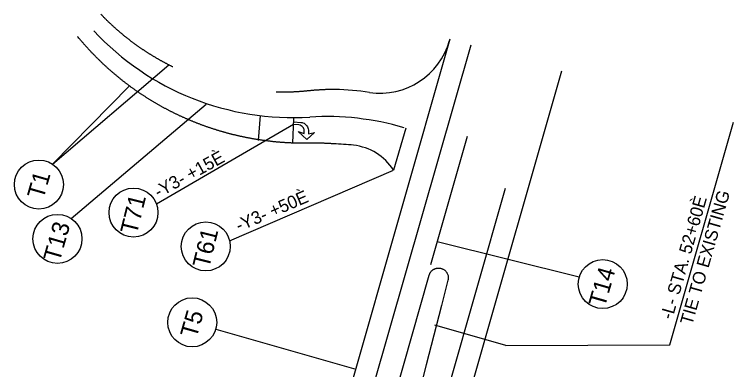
# Model space of a CAD drawing. Extents: x 1657109 to 2100937, y 684916 to 883211.
# Drawn here: x 2097689.9 to 2098086.6, y 689238.5 to 689434.2 of the extents above; entities that cross this region are included whole.
import ezdxf

# ---------------------------------------------------------------- set-up
doc = ezdxf.new("R2010")
doc.units = 0
for name, color, linetype in [('Prop CMT Pvmt Gravel', 7, 'Continuous'), ('Prop Conc 1ft 6in Curb and Gutter', 7, 'Continuous'), ('Prop Dimension', 7, 'Continuous'), ('Prop EOT', 7, 'Continuous'), ('Prop Guardrail Anchor Unit CELL', 7, 'Continuous'), ('Prop Lane Arrow CELL', 7, 'Continuous'), ('Prop Lane Lines', 7, 'Continuous'), ('Prop VPT Ditch Grade Right Label', 7, 'Continuous'), ('Scratch_Level_1', 7, 'Continuous'), ('Scratch_Level_3', 7, 'Continuous'), ('Scratch_Level_7', 7, 'Continuous')]:
    doc.layers.add(name, color=color, linetype=linetype)

msp = doc.modelspace()

# ---------------------------------------------------------------- linework, layer by layer
at = {"layer": 'Prop CMT Pvmt Gravel'}
for p, q in [((2097710.91, 689351.72), (2097775.17, 689406.36)), ((2097710.91, 689351.72), (2097753.45, 689394.79)), ((2097721.18, 689321.79), (2097795.69, 689384.68)), ((2098051.51, 689252.14), (2098086.61, 689374.76)), ((2097808.62, 689309.54), (2097899.01, 689348.49)), ((2098001.44, 689289.41), (2097923.18, 689308.85)), ((2097801, 689260.87), (2097878.16, 689238.78)), ((2097960.95, 689251.85), (2098051.51, 689252.14))]:
    msp.add_line(p, q, dxfattribs=at)
msp.add_lwpolyline([(2097843.91, 689373.58), (2097843.91, 689373.5), (2097768.29, 689329.65)], dxfattribs=at)
for centre in [(2097703.42, 689340.49), (2097755.61, 689325.03), (2097713.68, 689310.57), (2097795.48, 689306.44), (2098014.42, 689285.68), (2097788.02, 689264.58)]:
    msp.add_circle(centre, 13.5, dxfattribs=at)
at = {"layer": 'Prop Conc 1ft 6in Curb and Gutter'}
msp.add_line((2097907.61, 689152.7), (2097960.79, 689338.5), dxfattribs=at)
at = {"layer": 'Prop Dimension'}
for p, q in [((2097825.5, 689378.49), (2097824.44, 689364.77)), ((2097843.51, 689363.33), (2097844.04, 689376.93)), ((2097960.95, 689251.85), (2097921.9, 689263.03))]:
    msp.add_line(p, q, dxfattribs=at)
at = {"layer": 'Prop EOT'}
for p, q in [((2097845.45, 689080.92), (2097941.81, 689417.52)), ((2097895.44, 689066.61), (2097991.8, 689403.2))]:
    msp.add_line(p, q, dxfattribs=at)
at = {"layer": 'Prop Guardrail Anchor Unit CELL'}
for centre, radius, start, end in [((2097891.53, 689430.85), 40, 261.7882, 344.0259), ((2097862.25, 689227.95), 165, 81.7882, 88.4209), ((2097862.25, 689227.95), 135, 83.7241, 88.4209), ((2097873.73, 689332.32), 30, 32.5965, 83.7241)]:
    msp.add_arc(centre, radius, start, end, dxfattribs=at)
for points in [[(2097775.17, 689406.36), (2097774.62, 689406.65), (2097774.06, 689406.94), (2097773.5, 689407.23), (2097772.95, 689407.52), (2097772.4, 689407.82), (2097771.85, 689408.12), (2097771.3, 689408.42), (2097770.75, 689408.72), (2097770.2, 689409.03), (2097769.65, 689409.34), (2097769.11, 689409.65), (2097768.56, 689409.96), (2097768.02, 689410.28), (2097767.48, 689410.6), (2097766.94, 689410.92), (2097766.4, 689411.24), (2097765.86, 689411.57), (2097765.33, 689411.9), (2097764.79, 689412.23), (2097764.26, 689412.56), (2097763.73, 689412.9), (2097763.2, 689413.24), (2097762.67, 689413.58), (2097762.14, 689413.92), (2097761.61, 689414.27), (2097761.09, 689414.61), (2097760.57, 689414.97), (2097760.04, 689415.32), (2097759.52, 689415.67), (2097759.01, 689416.03), (2097758.49, 689416.39), (2097757.97, 689416.76), (2097757.46, 689417.12), (2097756.95, 689417.49), (2097756.44, 689417.86), (2097755.93, 689418.23), (2097755.42, 689418.61), (2097754.91, 689418.98), (2097754.41, 689419.36), (2097753.91, 689419.74), (2097753.4, 689420.13), (2097752.91, 689420.52), (2097752.41, 689420.9), (2097751.91, 689421.3), (2097751.42, 689421.69), (2097750.92, 689422.09), (2097750.43, 689422.48), (2097749.94, 689422.88), (2097749.46, 689423.29), (2097748.97, 689423.69), (2097748.48, 689424.1), (2097748, 689424.51), (2097747.52, 689424.92), (2097747.04, 689425.33), (2097746.57, 689425.75), (2097746.09, 689426.17), (2097745.62, 689426.59), (2097745.14, 689427.01), (2097744.67, 689427.44), (2097744.21, 689427.86), (2097743.74, 689428.29), (2097743.28, 689428.73), (2097742.81, 689429.16), (2097742.35, 689429.6), (2097741.89, 689430.03), (2097741.44, 689430.47), (2097740.98, 689430.92), (2097740.53, 689431.36), (2097740.05, 689431.84), (2097739.57, 689432.31), (2097739.09, 689432.79), (2097738.61, 689433.27), (2097737.65, 689434.22)], [(2097764.44, 689387.36), (2097763.82, 689387.74), (2097763.21, 689388.13), (2097762.6, 689388.52), (2097761.99, 689388.91), (2097761.38, 689389.3), (2097760.77, 689389.7), (2097760.17, 689390.09), (2097759.56, 689390.49), (2097758.96, 689390.9), (2097758.36, 689391.3), (2097757.77, 689391.71), (2097757.17, 689392.13), (2097756.58, 689392.54), (2097755.99, 689392.96), (2097755.4, 689393.38), (2097754.81, 689393.8), (2097754.23, 689394.22), (2097753.65, 689394.65), (2097753.06, 689395.08), (2097752.49, 689395.51), (2097751.91, 689395.95), (2097751.33, 689396.38), (2097750.76, 689396.82), (2097750.19, 689397.27), (2097749.62, 689397.71), (2097749.06, 689398.16), (2097748.49, 689398.61), (2097747.93, 689399.06), (2097747.37, 689399.51), (2097746.81, 689399.97), (2097746.26, 689400.43), (2097745.7, 689400.89), (2097745.15, 689401.36), (2097744.6, 689401.82), (2097744.05, 689402.29), (2097743.51, 689402.76), (2097742.97, 689403.24), (2097742.43, 689403.71), (2097741.89, 689404.19), (2097741.35, 689404.67), (2097740.82, 689405.16), (2097740.29, 689405.64), (2097739.76, 689406.13), (2097739.23, 689406.62), (2097738.71, 689407.11), (2097738.19, 689407.61), (2097737.67, 689408.1), (2097737.15, 689408.6), (2097736.64, 689409.1), (2097736.12, 689409.61), (2097735.61, 689410.11), (2097735.11, 689410.62), (2097734.6, 689411.13), (2097734.1, 689411.64), (2097733.6, 689412.16), (2097733.1, 689412.68), (2097732.6, 689413.2), (2097732.11, 689413.72), (2097731.62, 689414.24), (2097731.13, 689414.77), (2097730.64, 689415.29), (2097730.16, 689415.82), (2097729.68, 689416.35), (2097729.2, 689416.89), (2097728.72, 689417.42), (2097728.25, 689417.96), (2097727.78, 689418.5), (2097727.31, 689419.04), (2097726.87, 689419.56), (2097726.43, 689420.07), (2097725.99, 689420.58), (2097725.55, 689421.1), (2097724.67, 689422.12)], [(2097777.34, 689405.28), (2097776.85, 689405.52), (2097776.29, 689405.8), (2097775.73, 689406.08), (2097775.17, 689406.36)], [(2097866.8, 689392.89), (2097866.06, 689392.88), (2097865.31, 689392.87), (2097864.57, 689392.86), (2097863.83, 689392.84), (2097863.08, 689392.82), (2097862.34, 689392.79), (2097861.6, 689392.76), (2097860.86, 689392.73), (2097860.12, 689392.7), (2097859.37, 689392.66), (2097858.63, 689392.62), (2097857.89, 689392.57), (2097857.15, 689392.53), (2097856.41, 689392.47), (2097855.67, 689392.42), (2097854.93, 689392.36), (2097854.19, 689392.3), (2097853.45, 689392.23), (2097852.71, 689392.17), (2097851.98, 689392.09), (2097851.37, 689392.03), (2097850.76, 689391.97), (2097850.16, 689391.91), (2097849.55, 689391.86), (2097848.94, 689391.8), (2097848.33, 689391.75), (2097847.72, 689391.71), (2097847.11, 689391.66), (2097846.5, 689391.62), (2097845.88, 689391.58), (2097845.27, 689391.55), (2097844.66, 689391.51), (2097844.05, 689391.48), (2097843.44, 689391.45), (2097842.83, 689391.43), (2097842.21, 689391.41), (2097841.6, 689391.39), (2097840.99, 689391.37), (2097840.37, 689391.36), (2097839.76, 689391.35), (2097839.15, 689391.34), (2097838.53, 689391.33), (2097837.92, 689391.33), (2097837.31, 689391.33), (2097836.69, 689391.33), (2097836.08, 689391.34), (2097835.46, 689391.34), (2097834.85, 689391.35), (2097834.35, 689391.37)], [(2097814.23, 689367.12), (2097813.51, 689367.29), (2097812.79, 689367.45), (2097812.08, 689367.62), (2097811.37, 689367.79), (2097810.65, 689367.96), (2097809.94, 689368.14), (2097809.23, 689368.32), (2097808.52, 689368.51), (2097807.81, 689368.69), (2097807.1, 689368.88), (2097806.4, 689369.08), (2097805.69, 689369.27), (2097804.99, 689369.47), (2097804.28, 689369.68), (2097803.58, 689369.88), (2097802.88, 689370.09), (2097802.18, 689370.3), (2097801.48, 689370.52), (2097800.78, 689370.74), (2097800.08, 689370.96), (2097799.38, 689371.18), (2097798.69, 689371.41), (2097797.99, 689371.64), (2097797.3, 689371.87), (2097796.61, 689372.11), (2097795.92, 689372.35), (2097795.23, 689372.59), (2097794.54, 689372.84), (2097793.85, 689373.09), (2097793.17, 689373.34), (2097792.48, 689373.6), (2097791.8, 689373.86), (2097791.12, 689374.12), (2097790.44, 689374.38), (2097789.76, 689374.65), (2097789.08, 689374.92), (2097788.41, 689375.19), (2097787.73, 689375.47), (2097787.06, 689375.75), (2097786.38, 689376.03), (2097785.71, 689376.32), (2097785.04, 689376.61), (2097784.38, 689376.9), (2097783.71, 689377.19), (2097783.04, 689377.49), (2097782.38, 689377.79), (2097781.72, 689378.09), (2097781.06, 689378.4), (2097780.4, 689378.71), (2097779.74, 689379.02), (2097779.08, 689379.33), (2097778.43, 689379.65), (2097777.77, 689379.97), (2097777.12, 689380.3), (2097776.47, 689380.62), (2097775.82, 689380.95), (2097775.18, 689381.28), (2097774.53, 689381.62), (2097773.89, 689381.96), (2097773.25, 689382.3), (2097772.61, 689382.64), (2097771.97, 689382.99), (2097771.33, 689383.34), (2097770.7, 689383.69), (2097770.06, 689384.04), (2097769.43, 689384.4), (2097768.8, 689384.76), (2097768.17, 689385.12), (2097767.55, 689385.49), (2097766.92, 689385.86), (2097766.3, 689386.23), (2097765.68, 689386.6), (2097765.06, 689386.98), (2097764.44, 689387.36)], [(2097865.97, 689362.9), (2097865.37, 689362.95), (2097864.76, 689362.99), (2097864.15, 689363.03), (2097863.54, 689363.06), (2097862.93, 689363.09), (2097862.33, 689363.12), (2097861.72, 689363.15), (2097861.11, 689363.18), (2097860.5, 689363.2), (2097859.89, 689363.22), (2097859.28, 689363.23), (2097858.67, 689363.25), (2097858.06, 689363.26), (2097857.45, 689363.27), (2097856.84, 689363.27), (2097856.23, 689363.27), (2097855.62, 689363.27), (2097855, 689363.27), (2097854.39, 689363.26), (2097853.78, 689363.26), (2097853.04, 689363.24), (2097852.3, 689363.23), (2097851.56, 689363.22), (2097850.82, 689363.21), (2097850.08, 689363.21), (2097849.33, 689363.21), (2097848.59, 689363.21), (2097847.85, 689363.22), (2097847.11, 689363.23), (2097846.37, 689363.24), (2097845.63, 689363.26), (2097844.9, 689363.28), (2097844.16, 689363.31), (2097843.42, 689363.33), (2097842.68, 689363.36), (2097841.94, 689363.4), (2097841.2, 689363.43), (2097840.46, 689363.47), (2097839.73, 689363.52), (2097838.99, 689363.57), (2097838.25, 689363.62), (2097837.52, 689363.67), (2097836.78, 689363.73), (2097836.04, 689363.79), (2097835.31, 689363.85), (2097834.57, 689363.92), (2097833.84, 689363.99), (2097833.1, 689364.06), (2097832.37, 689364.14), (2097831.64, 689364.22), (2097830.91, 689364.3), (2097830.17, 689364.39), (2097829.44, 689364.48), (2097828.71, 689364.57), (2097827.98, 689364.67), (2097827.25, 689364.77), (2097826.52, 689364.87), (2097825.79, 689364.98), (2097825.06, 689365.09), (2097824.34, 689365.2), (2097823.61, 689365.32), (2097822.88, 689365.44), (2097822.16, 689365.56), (2097821.43, 689365.69), (2097820.71, 689365.82), (2097819.99, 689365.95), (2097819.26, 689366.08), (2097818.54, 689366.22), (2097817.82, 689366.37), (2097817.1, 689366.51), (2097816.38, 689366.66), (2097815.66, 689366.81), (2097814.94, 689366.97), (2097814.23, 689367.12)]]:
    msp.add_spline(points, degree=3, dxfattribs=at)
at = {"layer": 'Prop Lane Arrow CELL'}
msp.add_line((2097871.37, 689215.05), (2097930.27, 689420.82), dxfattribs=at)
at = {"layer": 'Prop Lane Lines'}
msp.add_line((2097905.82, 689371.49), (2097899.01, 689348.49), dxfattribs=at)
at = {"layer": 'Prop VPT Ditch Grade Right Label'}
msp.add_line((2097919.63, 689296.44), (2097939.86, 689367.11), dxfattribs=at)
at = {"layer": 'Scratch_Level_1'}
for centre, start, end in [((2097843.54, 689527.37), 222.9899, 273.5766), ((2097862.25, 689227.95), 73.5045, 93.5766)]:
    msp.add_arc(centre, 150, start, end, dxfattribs=at)
at = {"layer": 'Scratch_Level_3'}
msp.add_lwpolyline([(2097843.86, 689373.58), (2097843.99, 689375.08), (2097847.85, 689374.72), (2097848.56, 689374.62), (2097849.09, 689374.47), (2097849.66, 689374.23), (2097850.13, 689373.93), (2097850.49, 689373.63), (2097850.94, 689373.16), (2097851.24, 689372.76), (2097851.55, 689372.28), (2097851.85, 689371.66), (2097851.99, 689371.17), (2097852.12, 689370.52), (2097852.16, 689369.64), (2097852.05, 689368.43), (2097855.49, 689369.12), (2097851.25, 689365.24), (2097846.39, 689369.71), (2097849.68, 689368.65), (2097849.77, 689369.65), (2097849.79, 689370.21), (2097849.7, 689370.74), (2097849.55, 689371.16), (2097849.29, 689371.7), (2097849.04, 689372.08), (2097848.58, 689372.53), (2097848.04, 689372.86), (2097847.5, 689373.12), (2097846.72, 689373.32)], close=True, dxfattribs=at)
msp.add_lwpolyline([(2097843.86, 689373.58), (2097843.99, 689375.08), (2097847.85, 689374.72), (2097848.56, 689374.62), (2097849.09, 689374.47), (2097849.66, 689374.23), (2097850.13, 689373.93), (2097850.49, 689373.63), (2097850.94, 689373.16), (2097851.24, 689372.76), (2097851.55, 689372.28), (2097851.85, 689371.66), (2097851.99, 689371.17), (2097852.12, 689370.52), (2097852.16, 689369.64), (2097852.05, 689368.43), (2097855.49, 689369.12), (2097851.25, 689365.24), (2097846.39, 689369.71), (2097849.68, 689368.65), (2097849.77, 689369.65), (2097849.79, 689370.21), (2097849.7, 689370.74), (2097849.55, 689371.16), (2097849.29, 689371.7), (2097849.04, 689372.08), (2097848.58, 689372.53), (2097848.04, 689372.86), (2097847.5, 689373.12), (2097846.72, 689373.32)], close=True, dxfattribs=at)
at = {"layer": 'Scratch_Level_7'}
msp.add_lwpolyline([(2097889.95, 689190.03), (2097904.49, 689240.82), (2097918.74, 689290.62), (2097918.82, 689290.87), (2097918.9, 689291.08), (2097918.98, 689291.28), (2097919.05, 689291.43), (2097919.13, 689291.59), (2097919.35, 689291.99), (2097919.52, 689292.23), (2097919.61, 689292.36), (2097919.68, 689292.45), (2097919.79, 689292.58), (2097919.86, 689292.67), (2097920.06, 689292.89), (2097920.23, 689293.05), (2097920.4, 689293.2), (2097920.57, 689293.34), (2097920.76, 689293.49), (2097920.93, 689293.6), (2097921.06, 689293.69), (2097921.25, 689293.8), (2097921.54, 689293.95), (2097922.06, 689294.18), (2097922.32, 689294.26), (2097922.53, 689294.32), (2097922.68, 689294.36), (2097922.98, 689294.42), (2097923.38, 689294.47), (2097923.86, 689294.5), (2097924.08, 689294.49), (2097924.32, 689294.48), (2097924.58, 689294.45), (2097924.93, 689294.39), (2097925.33, 689294.3), (2097925.7, 689294.18), (2097925.93, 689294.09), (2097926.24, 689293.95), (2097926.44, 689293.85), (2097926.74, 689293.67), (2097926.99, 689293.5), (2097927.25, 689293.3), (2097927.48, 689293.11), (2097927.68, 689292.92), (2097927.89, 689292.69), (2097928.1, 689292.44), (2097928.4, 689292.02), (2097928.48, 689291.88), (2097928.68, 689291.53), (2097928.83, 689291.18), (2097928.99, 689290.76), (2097929.1, 689290.34), (2097929.17, 689289.99), (2097929.22, 689289.5), (2097929.23, 689289.29), (2097929.23, 689288.87), (2097929.18, 689288.38), (2097929.11, 689287.98), (2097929.07, 689287.82), (2097925.5, 689273.89), (2097917.13, 689241.23), (2097900.86, 689177.75)], dxfattribs=at)

# ---------------------------------------------------------------- texts
at = {"layer": 'Prop CMT Pvmt Gravel'}
for s, height, rotation, p in [('-Y3- +15È', 7, 28.7778, (2097769.37, 689332.94)), ('T1', 9.45, 74.0259, (2097705.9, 689331.99)), ('-Y3- +50È', 7, 23.3107, (2097813.79, 689314.41)), ('-L- STA. 52+60È', 7, 74.0259, (2098052.73, 689265.71)), ('TIE TO EXISTING', 7, 74.0259, (2098063.69, 689262.65)), ('T71', 9.45, 76.0867, (2097757.37, 689312.49)), ('T13', 9.45, 74.0259, (2097714.82, 689297.37)), ('T61', 9.45, 76.0867, (2097797.24, 689293.9)), ('T14', 9.45, 73.9702, (2098015.52, 689272.4)), ('T5', 9.45, 74.0259, (2097790.32, 689255.44))]:
    msp.add_text(s, height=height, rotation=rotation, dxfattribs=at).set_placement(p)

doc.saveas('drawing.dxf')
